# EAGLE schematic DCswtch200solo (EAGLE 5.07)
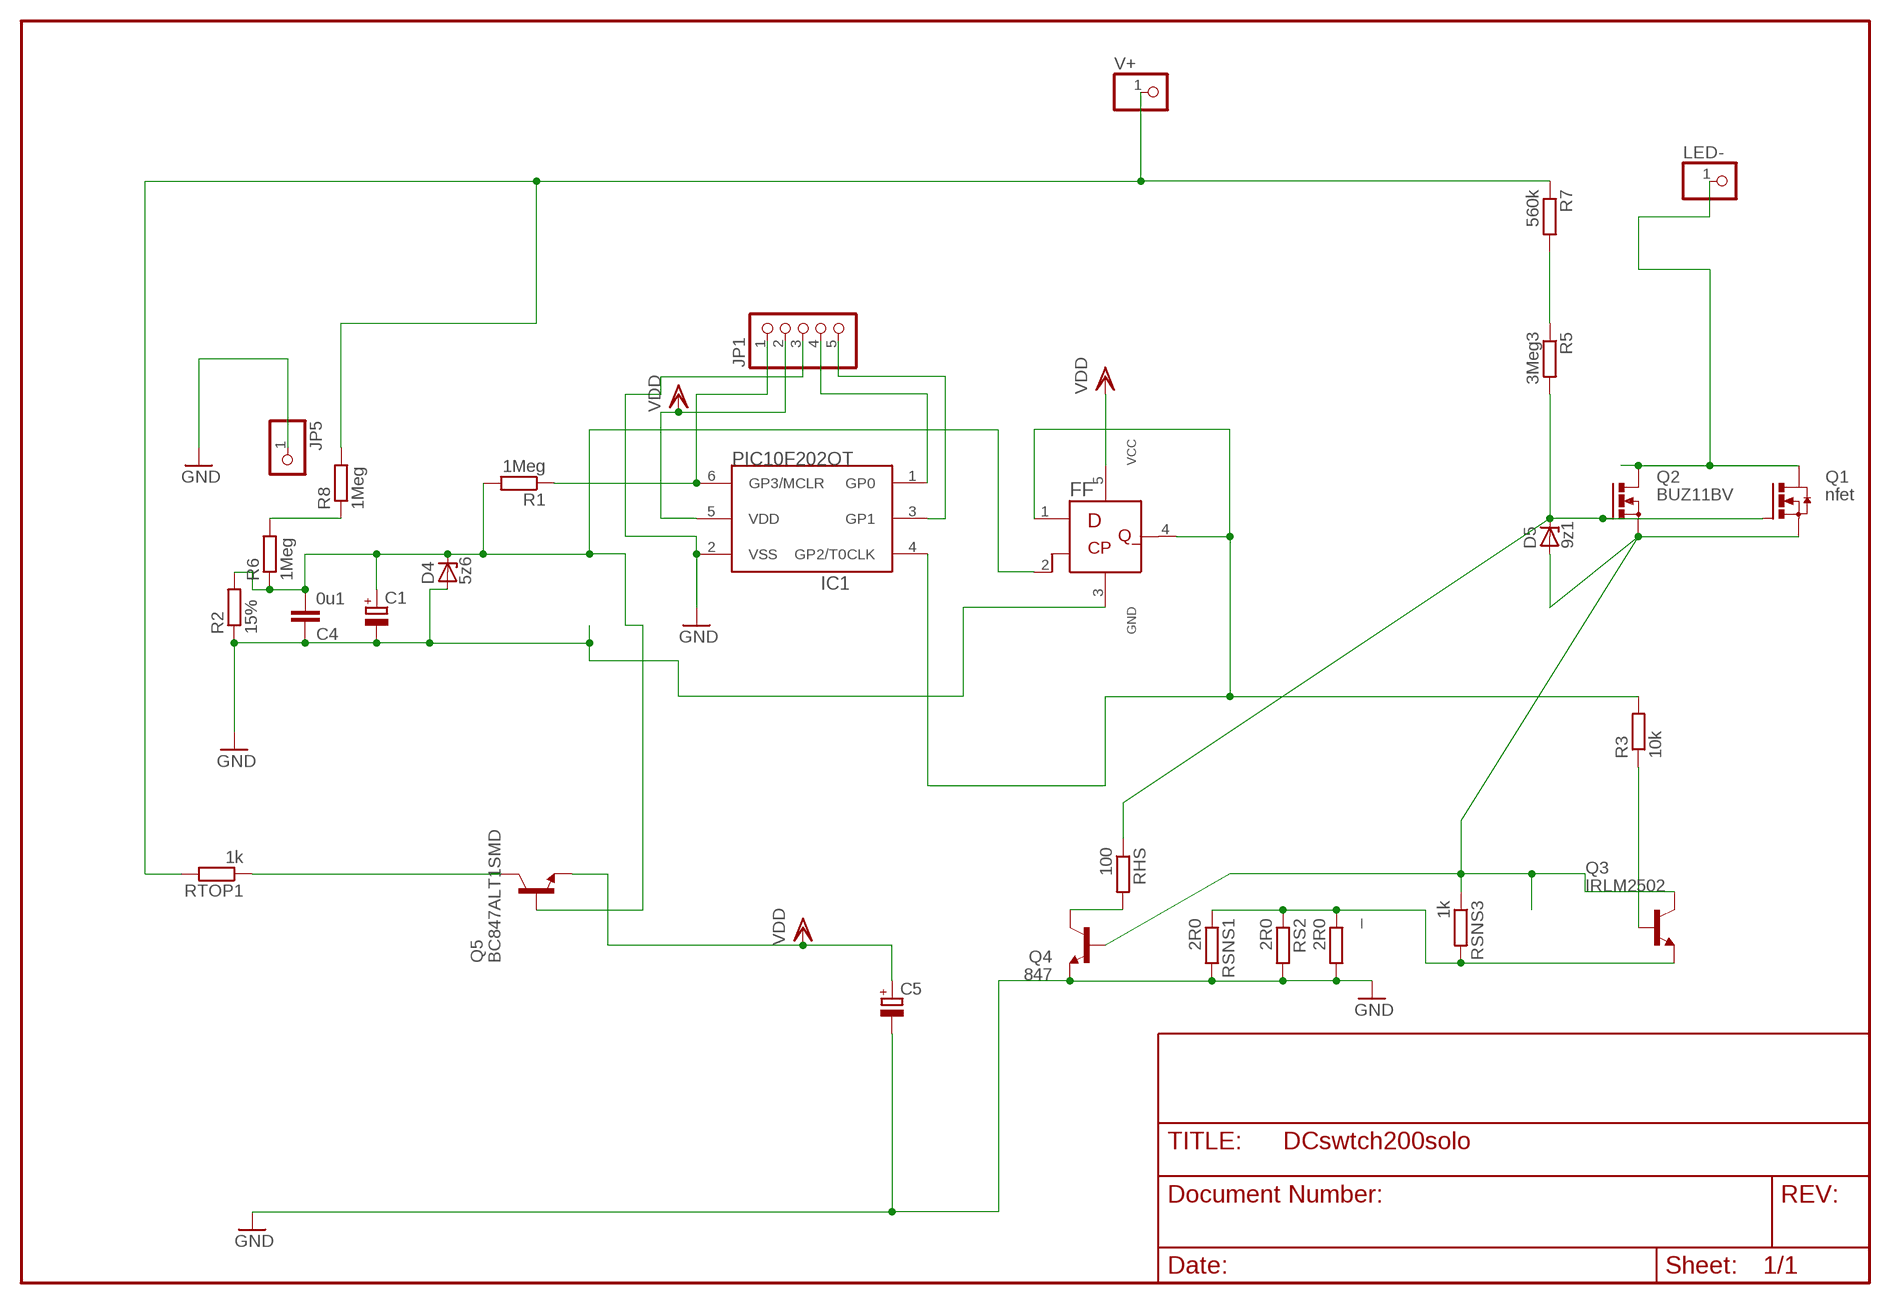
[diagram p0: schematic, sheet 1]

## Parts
_  2R0  R-EU_R2010  [R2010]
C1  CPOL-EUSMCA  [SMC_A]
C4  0u1  C-EUC1206  [C1206]
C5  CPOL-EUSANYO_SMD_C6  [SANYO-OSCON_SMD_C6]
D4  5z6  ZENER-DIODESOD80C  [SOD80C]
D5  9z1  ZENER-DIODESOD80C  [SOD80C]
FF  7479SOT23  [SOT23-5]
IC1  PIC10F202OT  [SOT23-6]
JP1  PINHD-1X5/90  [1X05/90]
JP5  PINHD-1X11MM6  [1X1MM8]
LED-  PINHD-1X11MM6  [1X1MM8]
Q1  nfet  N-HEXFET_DPAK-  [TO252]
Q2  BUZ11BV  [TO220BV]
Q3  IRLM2502  BC847ALT1SMD  [SOT23]
Q4  847  BC847ASMD  [SOT23]
Q5  BC847ALT1SMD  [SOT23]
R1  1Meg  R-EU_R0805  [R0805]
R2  15%  R-EU_R0805  [R0805]
R3  10k  R-EU_R0805  [R0805]
R5  3Meg3  R-EU_R1206  [R1206]
R6  1Meg  R-EU_R1206  [R1206]
R7  560k  R-EU_R1206  [R1206]
R8  1Meg  R-EU_R1206  [R1206]
RHS  100  R-EU_0204/5  [0204/5]
RS2  2R0  R-EU_R1206  [R1206]
RSNS1  2R0  R-EU_R2512  [R2512]
RSNS3  1k  R-EU_R1206  [R1206]
RTOP1  1k  R-EU_R1206  [R1206]
V+  PINHD-1X11MM6  [1X1MM8]

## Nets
BSW1: _.1 Q3.2(E) RS2.1 RSNS1.1 RSNS3.2
C: Q5.3(C) RTOP1.1
CB: C1.+ C4.2 D4.C FF.2(CP) Q5.1(B) R1.2 R2.2 R6.1
GND: _.2 C1.- C4.1 C5.- D4.A FF.3(GND) IC1.2(VSS) JP1.3 JP5.1 Q4.2(E) R2.1 RS2.2 RSNS1.2
LED-: LED-.1 Q1.3(D) Q2.D
N$1: D5.C Q1.1(G) Q2.G R5.2 RHS.1
N$2: FF.1(D) FF.4(Q_) IC1.4(GP2/T0CLK) R3.2
N$3: IC1.6(GP3/MCLR) JP1.1 R1.1
N$4: R5.1 R7.2
N$5: Q3.1(B) R3.1
N$7: Q4.3(C) RHS.2
N$9: R6.2 R8.1
N$10: IC1.1(GP0) JP1.4
N$12: IC1.3(GP1) JP1.5
S: D5.A Q1.2(S) Q2.S Q3.3(C) Q4.1(B) RSNS3.1
VDD: C5.+ FF.5(VCC) IC1.5(VDD) JP1.2 Q5.2(E)
VPLUS: R7.1 R8.2 RTOP1.2 V+.1

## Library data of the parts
_ R3 R5 R7 RHS RS2 RSNS1 RSNS3 RTOP1 = rcl:R-EU_: RESISTOR, European symbol
C1 = rcl:CPOL-EU: POLARIZED CAPACITOR, European symbol
C4 = rcl:C-EU: CAPACITOR, European symbol
C5 = rcl-2:CPOL-EU: POLARIZED CAPACITOR, European symbol
D4 D5 = diode:ZENER-DIODE: Z-Diode
FF = 74xx-little-de:7479
IC1 = microchip-5:PIC10F20*: uPC nW 0,25/0,5k Program Flash memory
JP1 = pinhead:PINHD-1X5: PIN HEADER
JP5 LED- V+ = pinhead:PINHD-1X1: PIN HEADER
Q1 = transistor-power:N-HEXFET_?-*: HEXFET® Power MOSFET
Q2 = transistor-power:BUZ11: N-CHANNEL MOS FET
Q3-Q5 = transistor-npn:BC847*: NPN Transistor
R1 R2 R6 R8 = rcl-2:R-EU_: RESISTOR, European symbol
